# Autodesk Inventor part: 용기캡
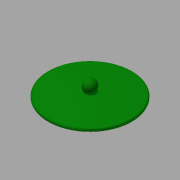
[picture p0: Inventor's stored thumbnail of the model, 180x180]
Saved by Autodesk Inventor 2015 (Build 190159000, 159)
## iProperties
Created: 2018-01
Part Number: 용기캡
Material: ABS 플라스틱
Document SubType Name: Modeling
Designer: mduedu
Density: 1 g/cm^3
Appearance: 진녹색
Author: mduedu
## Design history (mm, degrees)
sketch "스케치1"
  geometry: L1 (-35, 2.5)-(0, 2.5); L2 (0, 5)-(0, 0); L3 (0, 0)-(-35, 0); L4 (-35, 0)-(-35, 2.5); L5 (-31, 0)-(-29, 0); L6 (-29, 0)-(-29, -2); L7 (-29, -2)-(-31, -2); L8 (-31, -2)-(-31, 0); A1 r 246.25 centre (0, -241.25) between (0, 5) and (-35, 2.5); 1 further point
  constraints: 16 end point, 4 parallel, 2 horizontal, 2 perpendicular, 2 point on circle, 1 centre point, 1 coincident, 1 midpoint, 1 point on line, 1 vertical alignment
  dimensions: "d2" = 70 diameter of L4 L2; "d3" = 5 distance from line of L2.start L3; "d4" = 2.5 distance of L3.end L1.start; "d5" = 4 distance between parallel lines of L8 L4; "d6" = 2 distance of L6.end L7.end; "d7" = 2 distance between parallel lines of L7 L3
revolve "회전1" sketch "스케치1" stored, may be unused: angle "d8" = 90 deg
chamfer "모따기1" distance "d9" = 0.5; stored, may be unused: second distance "d10" = 2, angle "d11" = 45 deg
fillet "모깎기1" dims "d12" = 1
fillet "모깎기2" dims "d13" = 1
sketch "스케치2"
  geometry: L1 (-30.5, -2)-(-31, -1.5) reference; L2 (-31, -1.5)-(-31, 0) reference; L3 (-31, 0)-(-34, 0) reference; L4 (-35, 1)-(-35, 1.632) reference; L5 (35, 1.632)-(35, 1) reference; L6 (34, 0)-(31, 0) reference; L7 (31, 0)-(31, -1.5) reference; L8 (31, -1.5)-(30.5, -2) reference; L9 (30.5, -2)-(29, -2) reference; L10 (29, -2)-(29, -1) reference; L11 (28, 0)-(-28, 0) reference; L12 (-29, -1)-(-29, -2) reference; L13 (-29, -2)-(-30.5, -2) reference; L14 (0, 14)-(0, 4); A1 r 1 centre (-34, 1) between (-35, 1) and (-34, 0) reference; A2 r 1 centre (-34, 1.632) between (-34.139, 2.622) and (-35, 1.632) reference; A3 r 246.25 centre (0, -241.25) between (34.139, 2.622) and (-34.139, 2.622) reference; A4 r 1 centre (34, 1.632) between (35, 1.632) and (34.139, 2.622) reference; A5 r 1 centre (34, 1) between (34, 0) and (35, 1) reference; A6 r 1 centre (28, -1) between (29, -1) and (28, 0) reference; A7 r 1 centre (-28, -1) between (-28, 0) and (-29, -1) reference; A8 r 5 centre (0, 9) between (0, 14) and (0, 4); 3 further points
  constraints: 2 end point, 2 midpoint, 2 point on circle, 1 centre point, 1 coincident, 1 perpendicular, 1 point on line, 1 vertical alignment
  dimensions: "d14" = 10 diameter of A8; "d16" = 9 distance of A8.centre point (0, 0)
revolve "회전2" sketch "스케치2" stored, may be unused: angle "d17" = 90 deg
fillet "모깎기3" dims "d18" = 1
node "솔리드1"
node "절단 모서리 투영1"
